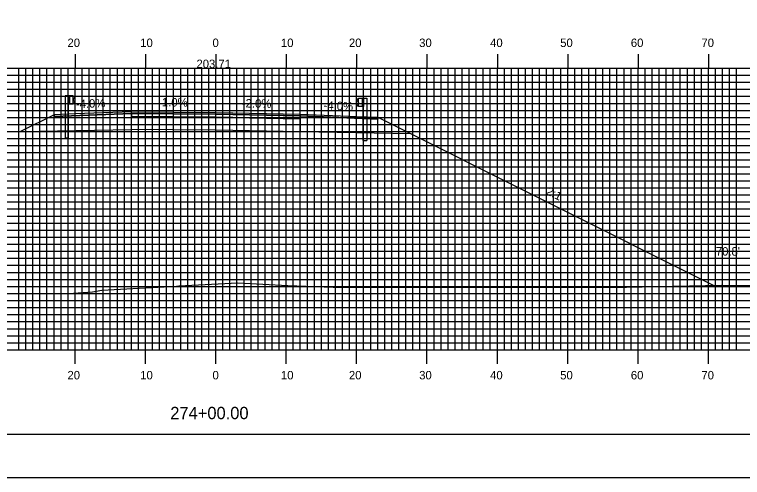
# Model space of a CAD drawing. Extents: x 1809406 to 1809749, y 442591 to 442811.
# Drawn here: x 1809543.2 to 1809646.7, y 442590.5 to 442656.3 of the extents above; entities that cross this region are included whole.
import ezdxf

# ---------------------------------------------------------------- set-up
doc = ezdxf.new("R2010")
doc.units = 0
for name, color, linetype in [('ANNOTATION', 7, 'Continuous'), ('BORDER', 7, 'Continuous'), ('D_Guardrail_Beam_Lt', 7, 'Continuous'), ('D_Guardrail_Beam_Rt', 7, 'Continuous'), ('D_Roadway_Centerline', 7, 'Continuous'), ('D_Roadway_Centerline_Text', 7, 'Continuous'), ('D_Roadway_Edge_Shoulder', 7, 'Continuous'), ('D_Roadway_Edge_TW', 7, 'Continuous'), ('D_Roadway_Pavement', 7, 'Continuous'), ('D_Roadway_SlopeLines', 7, 'Continuous'), ('D_Roadway_SubGrade', 7, 'Continuous'), ('D_Text_Standard', 7, 'Continuous'), ('H_V ANNOTATION', 7, 'Continuous'), ('MAJOR', 7, 'Continuous'), ('MINOR', 7, 'Continuous'), ('PLOT BOUNDARY', 7, 'Continuous'), ('S_Roadway_Centerline', 7, 'Continuous')]:
    doc.layers.add(name, color=color, linetype=linetype)

msp = doc.modelspace()

# ---------------------------------------------------------------- linework, layer by layer
at = {"layer": 'BORDER'}
msp.add_lwpolyline([(1809422.24, 442596.67), (1809742.24, 442596.67), (1809742.24, 442806.67), (1809422.24, 442806.67)], close=True, dxfattribs=at)
at = {"layer": 'D_Guardrail_Beam_Lt'}
for p, q in [((1809550.41, 442644.75), (1809550.41, 442638.75)), ((1809550.88, 442644.75), (1809550.41, 442644.75)), ((1809551.57, 442644.75), (1809550.88, 442644.75)), ((1809550.88, 442644.75), (1809550.88, 442643.58)), ((1809550.94, 442644.75), (1809550.94, 442643.58)), ((1809551.05, 442644.75), (1809551.05, 442643.58)), ((1809551.57, 442643.58), (1809551.57, 442644.75)), ((1809551.57, 442644.66), (1809551.64, 442644.65)), ((1809551.57, 442644.2), (1809551.57, 442644.13)), ((1809551.8, 442644.4), (1809551.6, 442644.26)), ((1809551.66, 442644.64), (1809551.8, 442644.54)), ((1809550.88, 442643.58), (1809551.57, 442643.58)), ((1809550.9, 442638.75), (1809550.9, 442643.58)), ((1809551.64, 442643.68), (1809551.57, 442643.66)), ((1809551.6, 442644.07), (1809551.8, 442643.93)), ((1809551.8, 442643.79), (1809551.66, 442643.69)), ((1809550.9, 442638.75), (1809550.41, 442638.75))]:
    msp.add_line(p, q, dxfattribs=at)
for centre, major_axis, start_param, end_param in [((1809551.65, 442644.2), (-0.0789, 0), 5.323254, 6.283185), ((1809551.63, 442644.61), (0.0417, 0), 0.959931, 1.376053), ((1809551.75, 442644.47), (0.0877, 0), 5.323254, 7.243116), ((1809551.65, 442644.13), (-0.0789, 0), 6.283185, 7.243116), ((1809551.63, 442643.72), (0.0417, 0), 4.907132, 5.323254), ((1809551.75, 442643.86), (0.0877, 0), 5.323254, 7.243116)]:
    msp.add_ellipse(centre, major_axis=major_axis, ratio=0.995501, start_param=start_param, end_param=end_param, dxfattribs=at)
at = {"layer": 'D_Guardrail_Beam_Rt'}
for p, q in [((1809592.02, 442644.29), (1809591.87, 442644.19)), ((1809592.11, 442644.31), (1809592.03, 442644.3)), ((1809592.11, 442644.39), (1809592.8, 442644.39)), ((1809592.11, 442643.23), (1809592.11, 442644.39)), ((1809592.63, 442644.39), (1809592.63, 442643.23)), ((1809592.73, 442644.39), (1809592.73, 442643.23)), ((1809592.8, 442644.39), (1809593.27, 442644.39)), ((1809592.8, 442644.39), (1809592.8, 442643.23)), ((1809593.27, 442644.39), (1809593.27, 442638.39)), ((1809591.87, 442644.05), (1809592.07, 442643.91)), ((1809592.07, 442643.71), (1809591.87, 442643.57)), ((1809591.87, 442643.43), (1809592.02, 442643.33)), ((1809592.03, 442643.32), (1809592.11, 442643.31)), ((1809592.1, 442643.85), (1809592.1, 442643.78)), ((1809592.8, 442643.23), (1809592.11, 442643.23)), ((1809592.77, 442638.39), (1809592.77, 442643.23)), ((1809592.77, 442638.39), (1809593.27, 442638.39))]:
    msp.add_line(p, q, dxfattribs=at)
for centre, major_axis, start_param, end_param in [((1809591.93, 442644.12), (-0.0877, 0), 5.323254, 7.243116), ((1809592.04, 442644.25), (-0.0417, 0), 4.907132, 5.323254), ((1809591.93, 442643.5), (-0.0877, 0), 5.323254, 7.243116), ((1809592.04, 442643.37), (-0.0417, 0), 0.959931, 1.376053), ((1809592.02, 442643.85), (0.0789, 0), 0, 0.959931), ((1809592.02, 442643.78), (0.0789, 0), 5.323254, 6.283185)]:
    msp.add_ellipse(centre, major_axis=major_axis, ratio=0.995501, start_param=start_param, end_param=end_param, dxfattribs=at)
at = {"layer": 'D_Roadway_Edge_Shoulder'}
for points in [[(1809559.84, 442642.48), (1809551.84, 442642.16), (1809551.84, 442642.16), (1809548.84, 442642.04), (1809548.84, 442641.79), (1809559.84, 442642.23)], [(1809583.84, 442642.13), (1809591.84, 442641.81), (1809591.84, 442641.81), (1809594.84, 442641.69), (1809594.84, 442641.44), (1809583.84, 442641.88)]]:
    msp.add_lwpolyline(points, close=True, dxfattribs=at)
at = {"layer": 'D_Roadway_Edge_TW'}
msp.add_lwpolyline([(1809559.84, 442642.23), (1809559.84, 442642.48), (1809571.84, 442642.37), (1809583.84, 442642.13), (1809583.84, 442641.88), (1809571.84, 442642.12)], close=True, dxfattribs=at)
at = {"layer": 'D_Roadway_Pavement'}
msp.add_lwpolyline([(1809559.84, 442641.82), (1809559.84, 442642.23), (1809571.84, 442642.12), (1809583.84, 442641.88), (1809583.84, 442641.46), (1809571.84, 442641.7)], close=True, dxfattribs=at)
for points in [[(1809559.84, 442642.23), (1809559.84, 442641.82)], [(1809583.84, 442641.88), (1809583.84, 442641.46)]]:
    msp.add_lwpolyline(points, dxfattribs=at)
at = {"layer": 'D_Roadway_SlopeLines'}
msp.add_lwpolyline([(1809594.84, 442641.69), (1809642.59, 442617.81)], dxfattribs=at)
at = {"layer": 'D_Roadway_SubGrade'}
for points in [[(1809559.84, 442641.82), (1809559.84, 442642.23), (1809548.84, 442641.79), (1809548.84, 442642.04), (1809544.09, 442639.67), (1809559.84, 442639.98)], [(1809559.84, 442639.98), (1809559.84, 442642.23), (1809559.84, 442641.82), (1809571.84, 442641.7), (1809583.84, 442641.46), (1809583.84, 442641.88), (1809583.84, 442639.63), (1809571.84, 442639.87)], [(1809583.84, 442641.46), (1809583.84, 442641.88), (1809594.84, 442641.44), (1809594.84, 442641.69), (1809599.59, 442639.32), (1809583.84, 442639.63)]]:
    msp.add_lwpolyline(points, close=True, dxfattribs=at)
at = {"layer": 'MAJOR'}
for p, q in [((1809551.84, 442650.67), (1809551.84, 442648.67)), ((1809561.84, 442650.67), (1809561.84, 442648.67)), ((1809571.84, 442650.67), (1809571.84, 442648.67)), ((1809581.84, 442650.67), (1809581.84, 442648.67)), ((1809591.84, 442650.67), (1809591.84, 442648.67)), ((1809601.84, 442650.67), (1809601.84, 442648.67)), ((1809611.84, 442650.67), (1809611.84, 442648.67)), ((1809621.84, 442650.67), (1809621.84, 442648.67)), ((1809631.84, 442650.67), (1809631.84, 442648.67)), ((1809641.84, 442650.67), (1809641.84, 442648.67)), ((1809431.84, 442648.67), (1809711.84, 442648.67)), ((1809431.84, 442648.67), (1809711.84, 442648.67)), ((1809551.84, 442608.67), (1809551.84, 442648.67)), ((1809561.84, 442608.67), (1809561.84, 442648.67)), ((1809571.84, 442608.67), (1809571.84, 442648.67)), ((1809581.84, 442608.67), (1809581.84, 442648.67)), ((1809591.84, 442608.67), (1809591.84, 442648.67)), ((1809601.84, 442608.67), (1809601.84, 442648.67)), ((1809611.84, 442608.67), (1809611.84, 442648.67)), ((1809621.84, 442608.67), (1809621.84, 442648.67)), ((1809631.84, 442608.67), (1809631.84, 442648.67)), ((1809641.84, 442608.67), (1809641.84, 442648.67)), ((1809431.84, 442643.67), (1809711.84, 442643.67)), ((1809431.84, 442638.67), (1809711.84, 442638.67)), ((1809431.84, 442633.67), (1809711.84, 442633.67)), ((1809431.84, 442628.67), (1809711.84, 442628.67)), ((1809431.84, 442623.67), (1809711.84, 442623.67)), ((1809431.84, 442618.67), (1809711.84, 442618.67)), ((1809431.84, 442613.67), (1809711.84, 442613.67)), ((1809431.84, 442608.67), (1809711.84, 442608.67)), ((1809431.84, 442608.67), (1809711.84, 442608.67)), ((1809551.84, 442606.66), (1809551.84, 442608.67)), ((1809561.84, 442606.66), (1809561.84, 442608.67)), ((1809571.84, 442606.66), (1809571.84, 442608.67)), ((1809581.84, 442606.66), (1809581.84, 442608.67)), ((1809591.84, 442606.66), (1809591.84, 442608.67)), ((1809601.84, 442606.66), (1809601.84, 442608.67)), ((1809611.84, 442606.66), (1809611.84, 442608.67)), ((1809621.84, 442606.66), (1809621.84, 442608.67)), ((1809631.84, 442606.66), (1809631.84, 442608.67)), ((1809641.84, 442606.66), (1809641.84, 442608.67))]:
    msp.add_line(p, q, dxfattribs=at)
at = {"layer": 'MINOR'}
for p, q in [((1809543.84, 442608.67), (1809543.84, 442648.67)), ((1809544.84, 442608.67), (1809544.84, 442648.67)), ((1809545.84, 442608.67), (1809545.84, 442648.67)), ((1809546.84, 442608.67), (1809546.84, 442648.67)), ((1809547.84, 442608.67), (1809547.84, 442648.67)), ((1809548.84, 442608.67), (1809548.84, 442648.67)), ((1809549.84, 442608.67), (1809549.84, 442648.67)), ((1809550.84, 442608.67), (1809550.84, 442648.67)), ((1809552.84, 442608.67), (1809552.84, 442648.67)), ((1809553.84, 442608.67), (1809553.84, 442648.67)), ((1809554.84, 442608.67), (1809554.84, 442648.67)), ((1809555.84, 442608.67), (1809555.84, 442648.67)), ((1809556.84, 442608.67), (1809556.84, 442648.67)), ((1809557.84, 442608.67), (1809557.84, 442648.67)), ((1809558.84, 442608.67), (1809558.84, 442648.67)), ((1809559.84, 442608.67), (1809559.84, 442648.67)), ((1809560.84, 442608.67), (1809560.84, 442648.67)), ((1809562.84, 442608.67), (1809562.84, 442648.67)), ((1809563.84, 442608.67), (1809563.84, 442648.67)), ((1809564.84, 442608.67), (1809564.84, 442648.67)), ((1809565.84, 442608.67), (1809565.84, 442648.67)), ((1809566.84, 442608.67), (1809566.84, 442648.67)), ((1809567.84, 442608.67), (1809567.84, 442648.67)), ((1809568.84, 442608.67), (1809568.84, 442648.67)), ((1809569.84, 442608.67), (1809569.84, 442648.67)), ((1809570.84, 442608.67), (1809570.84, 442648.67)), ((1809572.84, 442608.67), (1809572.84, 442648.67)), ((1809573.84, 442608.67), (1809573.84, 442648.67)), ((1809574.84, 442608.67), (1809574.84, 442648.67)), ((1809575.84, 442608.67), (1809575.84, 442648.67)), ((1809576.84, 442608.67), (1809576.84, 442648.67)), ((1809577.84, 442608.67), (1809577.84, 442648.67)), ((1809578.84, 442608.67), (1809578.84, 442648.67)), ((1809579.84, 442608.67), (1809579.84, 442648.67)), ((1809580.84, 442608.67), (1809580.84, 442648.67)), ((1809582.84, 442608.67), (1809582.84, 442648.67)), ((1809583.84, 442608.67), (1809583.84, 442648.67)), ((1809584.84, 442608.67), (1809584.84, 442648.67)), ((1809585.84, 442608.67), (1809585.84, 442648.67)), ((1809586.84, 442608.67), (1809586.84, 442648.67)), ((1809587.84, 442608.67), (1809587.84, 442648.67)), ((1809588.84, 442608.67), (1809588.84, 442648.67)), ((1809589.84, 442608.67), (1809589.84, 442648.67)), ((1809590.84, 442608.67), (1809590.84, 442648.67)), ((1809592.84, 442608.67), (1809592.84, 442648.67)), ((1809593.84, 442608.67), (1809593.84, 442648.67)), ((1809594.84, 442608.67), (1809594.84, 442648.67)), ((1809595.84, 442608.67), (1809595.84, 442648.67)), ((1809596.84, 442608.67), (1809596.84, 442648.67)), ((1809597.84, 442608.67), (1809597.84, 442648.67)), ((1809598.84, 442608.67), (1809598.84, 442648.67)), ((1809599.84, 442608.67), (1809599.84, 442648.67)), ((1809600.84, 442608.67), (1809600.84, 442648.67)), ((1809602.84, 442608.67), (1809602.84, 442648.67)), ((1809603.84, 442608.67), (1809603.84, 442648.67)), ((1809604.84, 442608.67), (1809604.84, 442648.67)), ((1809605.84, 442608.67), (1809605.84, 442648.67)), ((1809606.84, 442608.67), (1809606.84, 442648.67)), ((1809607.84, 442608.67), (1809607.84, 442648.67)), ((1809608.84, 442608.67), (1809608.84, 442648.67)), ((1809609.84, 442608.67), (1809609.84, 442648.67)), ((1809610.84, 442608.67), (1809610.84, 442648.67)), ((1809612.84, 442608.67), (1809612.84, 442648.67)), ((1809613.84, 442608.67), (1809613.84, 442648.67)), ((1809614.84, 442608.67), (1809614.84, 442648.67)), ((1809615.84, 442608.67), (1809615.84, 442648.67)), ((1809616.84, 442608.67), (1809616.84, 442648.67)), ((1809617.84, 442608.67), (1809617.84, 442648.67)), ((1809618.84, 442608.67), (1809618.84, 442648.67)), ((1809619.84, 442608.67), (1809619.84, 442648.67)), ((1809620.84, 442608.67), (1809620.84, 442648.67)), ((1809622.84, 442608.67), (1809622.84, 442648.67)), ((1809623.84, 442608.67), (1809623.84, 442648.67)), ((1809624.84, 442608.67), (1809624.84, 442648.67)), ((1809625.84, 442608.67), (1809625.84, 442648.67)), ((1809626.84, 442608.67), (1809626.84, 442648.67)), ((1809627.84, 442608.67), (1809627.84, 442648.67)), ((1809628.84, 442608.67), (1809628.84, 442648.67)), ((1809629.84, 442608.67), (1809629.84, 442648.67)), ((1809630.84, 442608.67), (1809630.84, 442648.67)), ((1809632.84, 442608.67), (1809632.84, 442648.67)), ((1809633.84, 442608.67), (1809633.84, 442648.67)), ((1809634.84, 442608.67), (1809634.84, 442648.67)), ((1809635.84, 442608.67), (1809635.84, 442648.67)), ((1809636.84, 442608.67), (1809636.84, 442648.67)), ((1809637.84, 442608.67), (1809637.84, 442648.67)), ((1809638.84, 442608.67), (1809638.84, 442648.67)), ((1809639.84, 442608.67), (1809639.84, 442648.67)), ((1809640.84, 442608.67), (1809640.84, 442648.67)), ((1809642.84, 442608.67), (1809642.84, 442648.67)), ((1809643.84, 442608.67), (1809643.84, 442648.67)), ((1809644.84, 442608.67), (1809644.84, 442648.67)), ((1809645.84, 442608.67), (1809645.84, 442648.67)), ((1809431.84, 442647.67), (1809711.84, 442647.67)), ((1809431.84, 442646.67), (1809711.84, 442646.67)), ((1809431.84, 442645.67), (1809711.84, 442645.67)), ((1809431.84, 442644.67), (1809711.84, 442644.67)), ((1809431.84, 442642.67), (1809711.84, 442642.67)), ((1809431.84, 442641.67), (1809711.84, 442641.67)), ((1809431.84, 442640.67), (1809711.84, 442640.67)), ((1809431.84, 442639.67), (1809711.84, 442639.67)), ((1809431.84, 442637.67), (1809711.84, 442637.67)), ((1809431.84, 442636.67), (1809711.84, 442636.67)), ((1809431.84, 442635.67), (1809711.84, 442635.67)), ((1809431.84, 442634.67), (1809711.84, 442634.67)), ((1809431.84, 442632.67), (1809711.84, 442632.67)), ((1809431.84, 442631.67), (1809711.84, 442631.67)), ((1809431.84, 442630.67), (1809711.84, 442630.67)), ((1809431.84, 442629.67), (1809711.84, 442629.67)), ((1809431.84, 442627.67), (1809711.84, 442627.67)), ((1809431.84, 442626.67), (1809711.84, 442626.67)), ((1809431.84, 442625.67), (1809711.84, 442625.67)), ((1809431.84, 442624.67), (1809711.84, 442624.67)), ((1809431.84, 442622.67), (1809711.84, 442622.67)), ((1809431.84, 442621.67), (1809711.84, 442621.67)), ((1809431.84, 442620.67), (1809711.84, 442620.67)), ((1809431.84, 442619.67), (1809711.84, 442619.67)), ((1809431.84, 442617.67), (1809711.84, 442617.67)), ((1809431.84, 442616.67), (1809711.84, 442616.67)), ((1809431.84, 442615.67), (1809711.84, 442615.67)), ((1809431.84, 442614.67), (1809711.84, 442614.67)), ((1809431.84, 442612.67), (1809711.84, 442612.67)), ((1809431.84, 442611.67), (1809711.84, 442611.67)), ((1809431.84, 442610.67), (1809711.84, 442610.67)), ((1809431.84, 442609.67), (1809711.84, 442609.67))]:
    msp.add_line(p, q, dxfattribs=at)
at = {"layer": 'PLOT BOUNDARY'}
msp.add_lwpolyline([(1809406.05, 442590.55), (1809746.05, 442590.55), (1809746.05, 442810.55), (1809406.05, 442810.55)], close=True, dxfattribs=at)
at = {"layer": 'S_Roadway_Centerline'}
msp.add_lwpolyline([(1809531.99, 442616.66), (1809543.3, 442616.68), (1809550.95, 442616.68), (1809554.3, 442616.9), (1809555.63, 442617.14), (1809566.24, 442617.71), (1809566.6, 442617.74), (1809574.95, 442618.17), (1809582.08, 442617.78), (1809588.51, 442617.57), (1809630.2, 442617.59), (1809643.64, 442617.83), (1809668.67, 442617.8), (1809687.86, 442618.11), (1809698.57, 442618.34), (1809711.84, 442618.34)], dxfattribs=at)

# ---------------------------------------------------------------- texts
at = {"layer": 'ANNOTATION'}
for s, rotation, p in [('-4.0%', 2.2906, (1809551.97, 442642.97)), ('1.0%', 359.454, (1809564.17, 442643.24)), ('-2.0%', 358.8542, (1809575.52, 442643.1)), ('-4.0%', 357.7094, (1809587.13, 442642.8)), ('2:1', 333.4349, (1809618.65, 442630.82))]:
    msp.add_text(s, height=1.2, rotation=rotation, dxfattribs=at).set_placement(p)
at = {"layer": 'D_Roadway_Centerline'}
for s, p in [('C', (1809571.83, 442642.37)), ('L', (1809571.84, 442642.36))]:
    msp.add_text(s, height=0.0146, dxfattribs=at).set_placement(p)
at = {"layer": 'D_Roadway_Centerline_Text'}
msp.add_text('203.71', height=1.2, dxfattribs=at).set_placement((1809569.08, 442648.68))
at = {"layer": 'D_Text_Standard'}
msp.add_text("70.8'", height=1.2, dxfattribs=at).set_placement((1809642.89, 442622.05))
at = {"layer": 'H_V ANNOTATION'}
for s, height, p in [('20', 1.2, (1809550.75, 442651.67)), ('10', 1.2, (1809561.09, 442651.67)), ('0', 1.2, (1809571.36, 442651.67)), ('10', 1.2, (1809581.09, 442651.67)), ('20', 1.2, (1809590.75, 442651.67)), ('30', 1.2, (1809600.73, 442651.67)), ('40', 1.2, (1809610.81, 442651.67)), ('50', 1.2, (1809620.77, 442651.67)), ('60', 1.2, (1809630.81, 442651.67)), ('70', 1.2, (1809640.84, 442651.67)), ('20', 1.2, (1809550.75, 442604.47)), ('10', 1.2, (1809561.09, 442604.47)), ('0', 1.2, (1809571.36, 442604.47)), ('10', 1.2, (1809581.09, 442604.47)), ('20', 1.2, (1809590.75, 442604.47)), ('30', 1.2, (1809600.73, 442604.47)), ('40', 1.2, (1809610.81, 442604.47)), ('50', 1.2, (1809620.77, 442604.47)), ('60', 1.2, (1809630.81, 442604.47)), ('70', 1.2, (1809640.84, 442604.47)), ('274+00.00', 1.75, (1809565.36, 442598.82))]:
    msp.add_text(s, height=height, dxfattribs=at).set_placement(p)

doc.saveas('drawing.dxf')
